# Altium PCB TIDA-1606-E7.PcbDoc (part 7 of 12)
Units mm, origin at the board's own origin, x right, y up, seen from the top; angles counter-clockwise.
Board outline 270 x 345 mm, 4 copper layers (Top Layer, Signal Layer 1, Signal Layer 2, Bottom Layer), stack 2.326 mm thick; 1282 components, 576 nets, 3628 pads, 4132 vias.
Unrouted connection lines stored in the file: 1719.
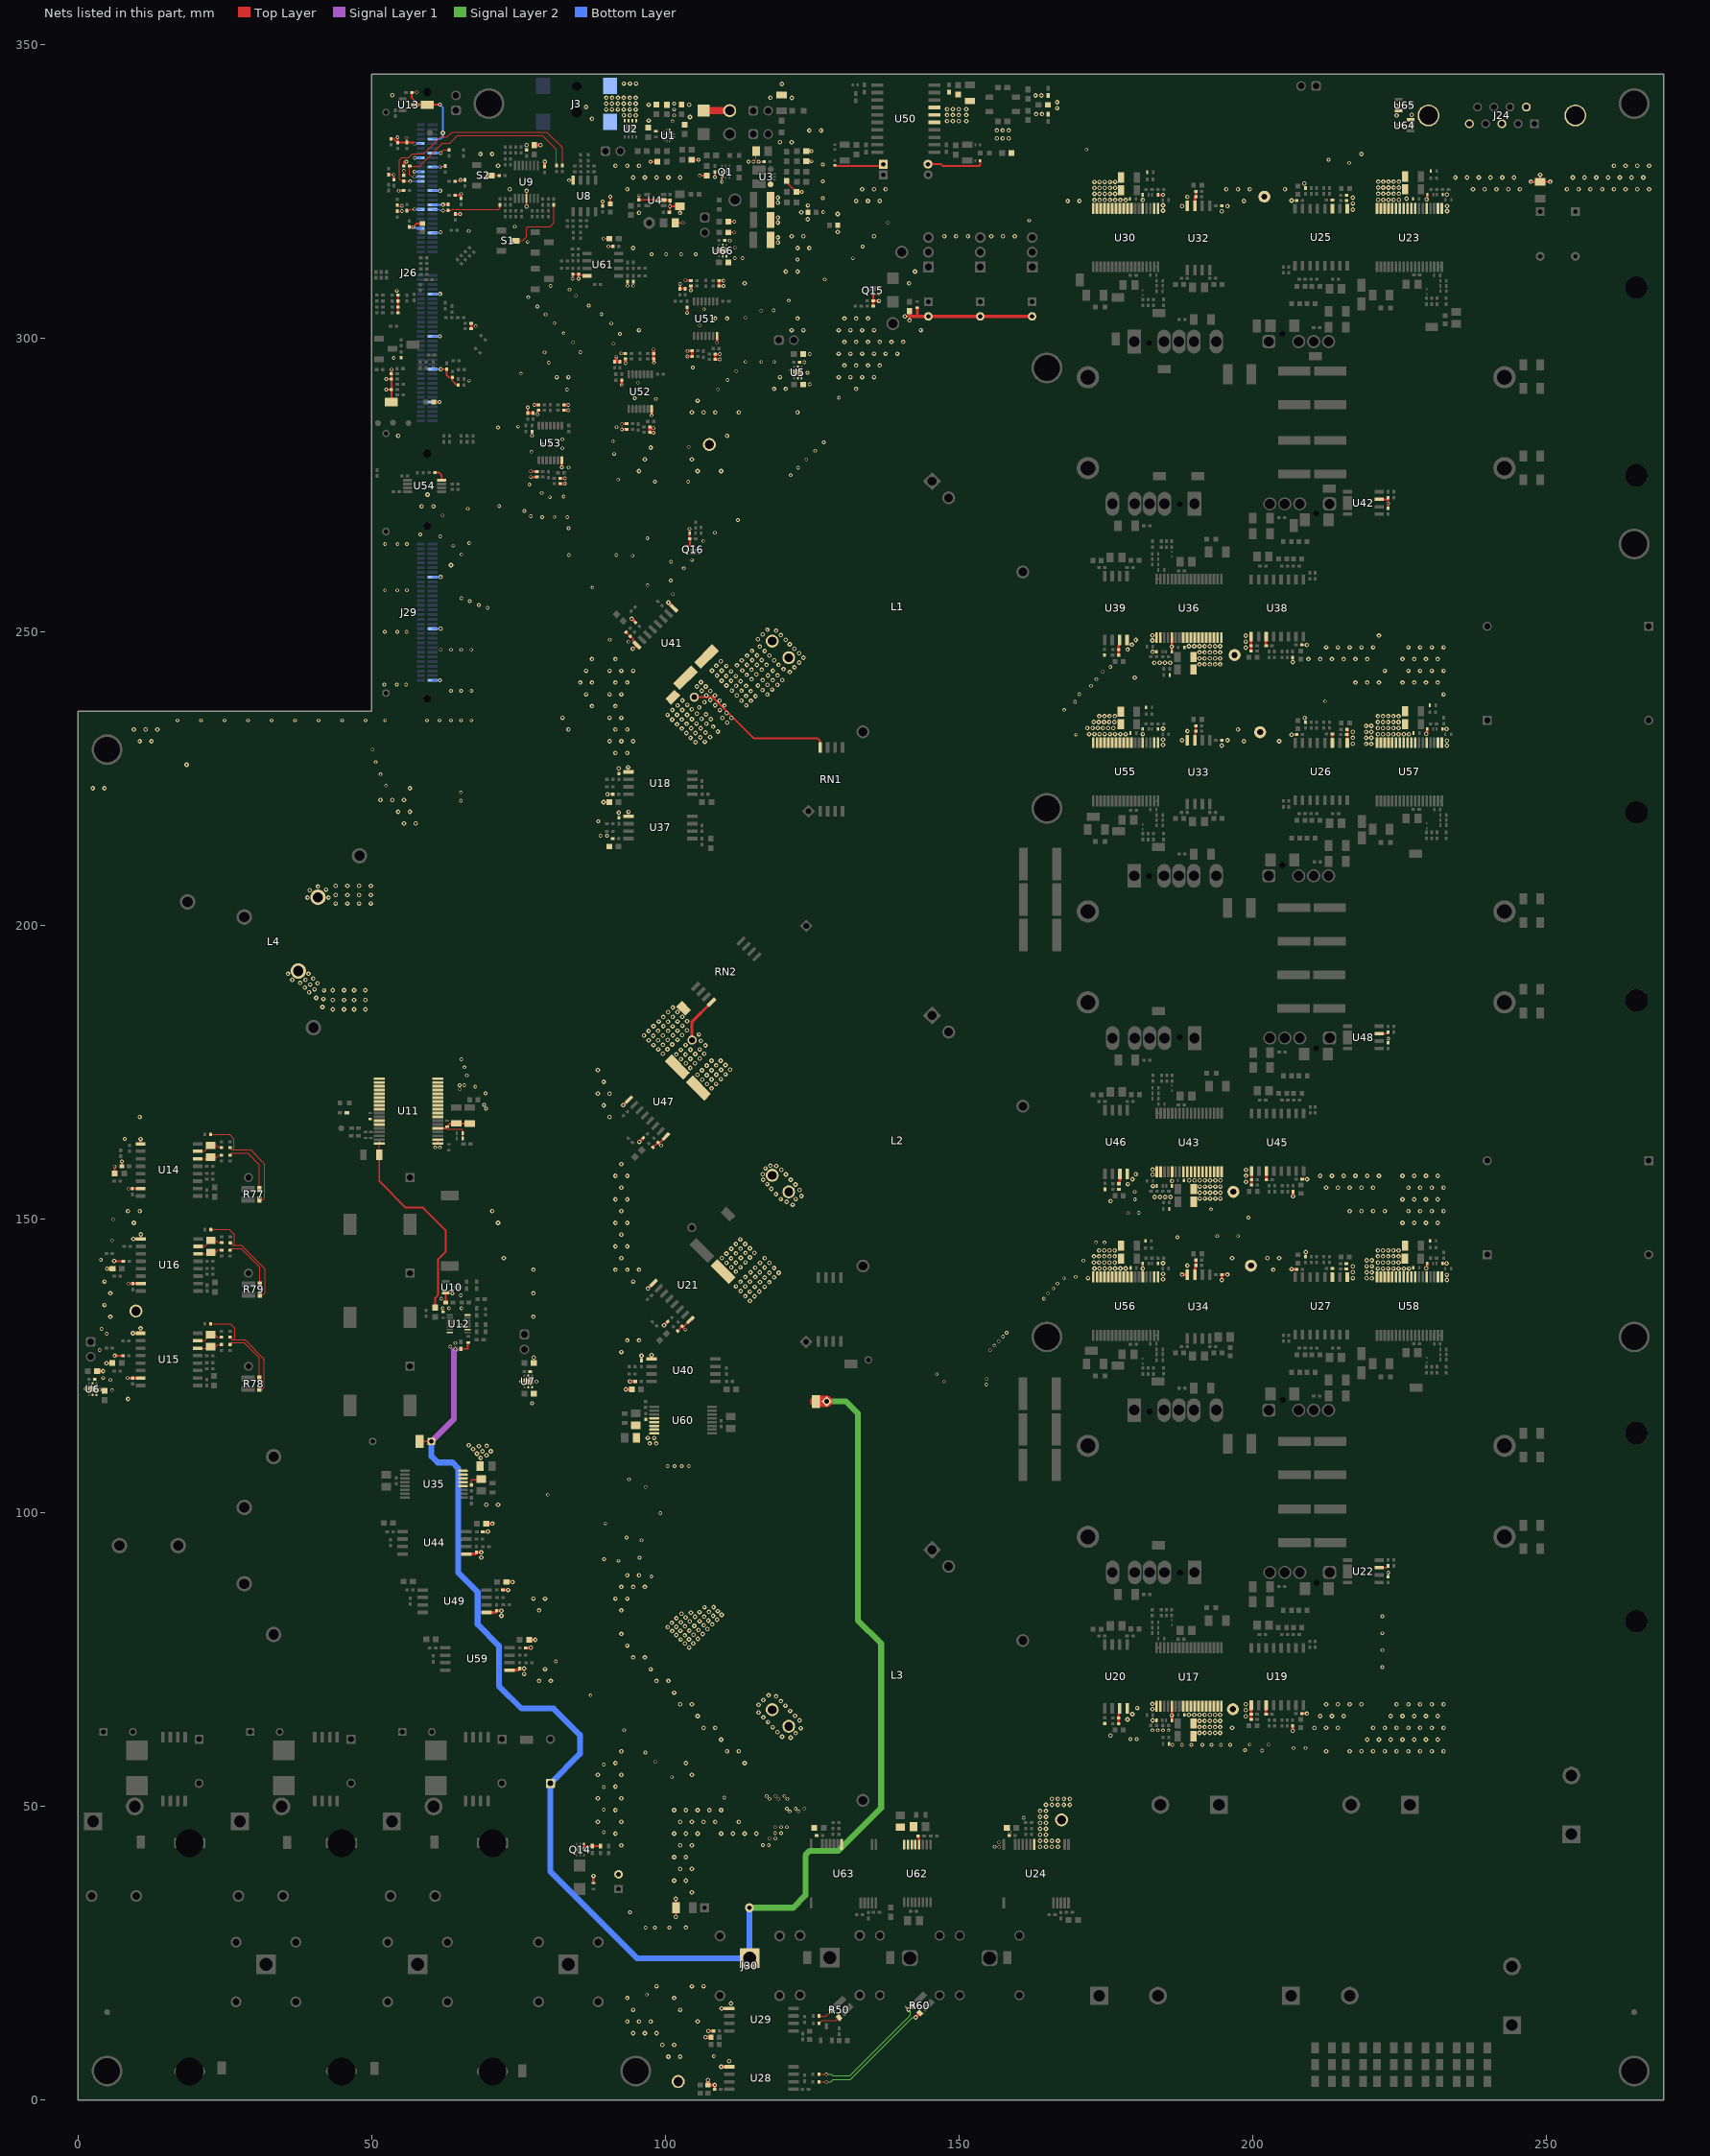
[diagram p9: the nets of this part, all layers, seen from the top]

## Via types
v1: diameter 0.762, hole 0.356, Top Layer to Bottom Layer, tented both sides, 2905 vias
v2: diameter 0.61, hole 0.356, Top Layer to Bottom Layer, tented both sides, 1212 vias
v3: diameter 0.864, hole 0.406, Top Layer to Bottom Layer, tented both sides, 15 vias

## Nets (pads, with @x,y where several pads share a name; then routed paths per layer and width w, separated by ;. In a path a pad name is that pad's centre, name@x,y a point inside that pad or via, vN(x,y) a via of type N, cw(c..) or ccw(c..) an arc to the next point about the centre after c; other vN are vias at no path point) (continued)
GND: C1.2 C2.2 C3.2 C4.2 C5.2 C6.2 C9.2 C10.2 C11.2 C12.2 C13.1 C14.2 C15.2 C16.2 C17.2 C18.2 C19.2 C20.2 C21.1 C22.2 C23.2 C24.2 C25.2 C26.2 C27.2 C28.1 C29.2 C30.2 C31.2 C32.1 C34.2 C58.1 C59.2 C61.2 C62.2 C65.1 C66.2 C85.2 C86.2 C87.2 C94.2 C95.2 C98.2 C102.2 C103.2 C104.2 C107.1 C110.2 C112.1 C116.1 C119.2 C121.1 C125.1 C128.2 C130.1 C132.2 C133.2 C134.2 C143.2 C146.2 C154.2 C155.2 C157.1 C158.2 C159.2 C162.2 C166.2 C168.2 C170.1 C171.2 C172.2 C173.2 C174.2 C180.2 C183.2 C186.2 C194.2 C195.2 C199.2 C207.2 C208.2 C211.1 C212.2 C220.2 C221.2 C225.2 C226.2 C227.2 C229.2 C232.2 C233.2 C234.2 C240.2 C243.2 C246.2 C249.2 C253.2 C256.2 C260.2 C263.2 C267.2 C269.2 C271.2 C274.2 C276.2 C277.2 C278.2 C283.1 C284.2 C285.2 C287.2 C290.2 C292.2 C298.2 C299.2 C301.2 C302.2 C303.2 C306.2 C310.2 C311.2 C312.2 C314.1 C315.1 C317.2 C318.2 C319.2 C320.2 C321.2 C322.1 C323.2 C326.2 C327.2 C328.2 C329.2 C330.2 C333.2 C338.2 C340.1 C341.2 C344.1 C345.1 C346.2 C348.2 C349.2 C351.2 C355.1 C356.2 C358.2 C359.2 C360.2 C363.2 C364.2 C365.2 C366.2 C367.2 C368.2 C369.2 C383.1 C384.1 C385.2 C386.2 C387.2 C388.2 C389.2 C390.2 C391.2 C392.2 C393.1 C394.2 C397.2 C398.2 C399.2 C401.2 C402.2 C405.2 C406.2 C407.2 C409.1 C410.2 C413.2 C414.2 C415.2 C417.2 C418.2 C421.2 C422.2 C423.2 C425.2 C426.2 C429.2 C430.2 C431.2 C432.2 C433.2 C434.2 C435.2 C436.2 C437.2 C438.2 C439.2 C440.2 C441.2 C442.2 C443.2 C444.1 C445.2 C448.2 C449.2 C450.2 C451.2 C452.2 C461.2 C462.2 C463.2 C464.2 C465.2 C466.2 C467.2 C468.2 C469.1 C470.2 C471.2 C472.2 C473.2 C474.2 C475.1 C476.1 C477.1 C478.1 C479.1 C480.1 C481.1 C483.2 C484.2 C485.2 C486.2 C487.2 C488.2 C489.2 C490.2 C492.2 D2.2 FB20.1 J3.2 J3.3 J23.1 J26.10 J26.24 J26.38 J26.56 J26.74 J26.75 J26.83 J26.86 J26.92 J26.99 J26.102 J26.105 J26.108 J26.111 J26.114 J29.2 J29.24 J29.46 L6.1 L9.1 Q1.4 Q1.7 Q14.4 Q14.7 Q15.4 Q15.7 Q16.4 Q16.7 R3.1 R4.1 R8.1 R9.1 R13.1 R14.2 R15.1 R18.1 R19.2 R29.2 R111.1 R115.1 R131.1 R152.1 R158.1 R175.2 R185.2 R193.1 R197.1 R212.1 R227.1 R255.1 R261.2 R265.2 R269.2 R282.1 R288.1 R299.2 R305.2 R314.2 R321.1 R327.1 R337.2 R342.1 R344.2 R375.1 R376.1 R377.1 R378.1 R379.1 R381.1 R389.1 R392.1 R398.1 R403.1 R413.1 R414.1 R415.1 R422.1 R424.1 R434.2 R441.1 R442.1 R443.1 R444.1 R512.1 R532.1 R540.1 TP2.1 TP4.1 TP8.1 TP10.1 TP11.1 TP12.1 TP13.1 TP14.1 TP15.1 TP17.1 TP20.1 TP23.1 TP26.1 U1.8 U2.5 U2.6 U2.7 U2.8 U3.4 U4.2 U5.2 U5.3 U5.5 U5.7@122.588,294.218 U6.2 U6.3 U6.5 U6.7@2.55,121.112 U7.2 U7.3 U7.5 U7.7@76.69,122.401 U8.4 U9.11 U11.1 U11.2 U11.5 U11.8 U11.9 U11.10 U11.11 U11.12 U11.13 U11.14 U11.15 U11.16 U11.17 U11.18 U13.3 U14.9 U14.15 U15.9 U15.15 U16.9 U16.15 U17.1 U17.2 U17.5 U17.8 U17.9 U17.10 U17.11 U17.12 U17.13 U17.14 U17.15 U17.16 U17.17 U17.18 U18.5 U19.9 U19.11 U20.3 U20.4 U21.3 U21.10 U22.3 U23.1 U23.2 U23.5 U23.8 U23.9 U23.10 U23.11 U23.12 U23.13 U23.14 U23.15 U23.16 U23.17 U23.18 U24.9 U25.9 U25.11 U26.9 U26.11 U27.9 U27.11 U28.5 U29.5 U30.1 U30.2 U30.5 U30.8 U30.9 U30.10 U30.11 U30.12 U30.13 U30.14 U30.15 U30.16 U30.17 U30.18 U32.3 U32.4 U33.3 U33.4 U34.3 U34.4 U35.4 U35.5 U35.6 U35.7 U35.8 U36.1 U36.2 U36.5 U36.8 U36.9 U36.10 U36.11 U36.12 U36.13 U36.14 U36.15 U36.16 U36.17 U36.18 U37.5 U38.9 U38.11 U39.3 U39.4 U40.5 U41.3 U41.10 U42.3 U43.1 U43.2 U43.5 U43.8 U43.9 U43.10 U43.11 U43.12 U43.13 U43.14 U43.15 U43.16 U43.17 U43.18 U44.5 U45.9 U45.11 U46.3 U46.4 U47.3 U47.10 U48.3 U49.5 U51.7 U52.7 U53.7 U54.4 U55.1 U55.2 U55.5 U55.8 U55.9 U55.10 U55.11 U55.12 U55.13 U55.14 U55.15 U55.16 U55.17 U55.18 U56.1 U56.2 U56.5 U56.8 U56.9 U56.10 U56.11 U56.12 U56.13 U56.14 U56.15 U56.16 U56.17 U56.18 U57.1 U57.2 U57.5 U57.8 U57.9 U57.10 U57.11 U57.12 U57.13 U57.14 U57.15 U57.16 U57.17 U57.18 U58.1 U58.2 U58.5 U58.8 U58.9 U58.10 U58.11 U58.12 U58.13 U58.14 U58.15 U58.16 U58.17 U58.18 U59.5 U60.4 U60.5 U60.6 U60.7 U60.8 U61.4 U62.4 U62.5 U62.6 U62.7 U62.8 U63.9 U66.2 U66.3 U66.5 U66.7@109.817,314.983 | length 350.7
  Top Layer w0.203: C490.2@54.402,321.7 v2(55.186,321.7) ; C485.2@54.402,322.585 v2(55.178,322.585) ; v2(54.647,325.185) C358.2@55.469,325.185 ; C227.2@55.502,327.785 v2(55.502,328.586) ; C487.2@56.002,321.785 56.37,321.785 56.584,321.999 v2(57.317,321.999) ; v2(61.688,329.185) 61.873,329.37 C61.2@62.602,329.37 ; v2(61.802,331.585) 62.309,332.092 C240.2@63.202,332.092 ; 62.611,165.521 62.778,165.354 65.346,165.354 65.532,165.168 R111.1@65.532,163.802 ; C486.2@64.227,326.8 64.988,326.8 v2(65.188,327) C488.2@65.902,327 ; 66.974,302.117 v2(67.761,302.117) ; v2(83.66,326.954) U8.4@84.347,326.954 ; v2(115.058,330.1) 115.504,330.546 C12.2@115.504,331.894 ; v2(115.914,330.1) C13.1@116.844,330.1
  Top Layer w0.229: v2@8.493,155.239 C107.1@9.331,155.239 9.342,155.25 U14.15@10.691,155.25 ; v1@181.33,141.63 C410.2@181.33,142.505 ; U33.3@190.197,231.6 190.197,232.684 190.377,232.864 C256.2@190.377,233.174 R265.2@190.377,234.071 ; v1@206.87,244.698 v1(206.87,244.898) C298.2@206.87,245.698 ; C299.2@208.418,247.819 v1(209.27,247.819) ; U26.11@213.612,231.14 C477.1@213.612,232.641 ; R212.1@216.095,233.429 216.152,233.372 U26.9@216.152,231.14 ; R540.1@232.356,142.505 v1(233.054,142.505)
  Top Layer w0.254: C103.2@52.902,327.914 v2@53.746,327.914 ; C326.2@53.802,327.025 v2(53.802,327.857) ; C274.2@55.51,329.37 55.51,330.101 55.524,330.115 v2(55.935,330.115) ; C387.2@63.778,293.4 63.778,292.824 64.502,292.1 C386.2@64.802,292.1 ; v1(76.402,322.474) U9.11@76.402,323.868 v1(76.402,325.157) ; v2(84.27,310.177) R19.2@84.27,310.962 C32.1@85.27,310.962 ; v2(85.27,310.198) C32.1@85.27,310.962 ; U61.4@86.702,310.684 85.898,310.684 85.62,310.962 C32.1@85.27,310.962 ; v2(93.597,308.998) C444.1@93.597,309.684 ; v2(94.57,309) R29.2@94.57,309.684 ; v2(109.679,326.695) Q1.7@109.679,328.3 ; R13.1@120.702,326.612 R18.1@122.337,324.977
  Top Layer w0.305: v1(4.9,125.5) 5.844,125.5 C119.2@5.876,125.532 ; v1(5,141.6) 5.913,141.6 C128.2@5.918,141.605 ; v1(6.2,142.9) 7.729,142.9 C130.1@7.754,142.875 ; v1(6.3,126.8) 7.704,126.8 7.709,126.805 C121.1@7.712,126.802 ; C110.2@6.3,158.214 v2(6.3,159) ; C112.1@7.512,159.06 v2(7.512,159.868) ; v1(9.388,130.612) U15.9@10.691,130.612 v1(10.691,131.455) ; v1(9.458,146.685) U16.9@10.733,146.685 v1(10.733,147.455) ; U14.9@10.691,162.87 v1(10.691,163.691) ; v2(52.522,291.3) C392.2@53.402,291.3 ; v2(52.522,293.091) C391.2@53.402,293.091 ; C158.2@53.34,334.016 53.808,334.016 C317.2@54.457,333.367 ; TP15.1@53.402,289.185 C392.2@53.402,291.3 ; v2(53.402,294.711) C390.2@53.402,293.976 C391.2@53.402,293.091 ; v2@53.746,327.914 v2(53.802,327.857) ; v2(54.457,334.284) C317.2@54.457,333.367 ; R444.1@54.524,304.385 R443.1@54.524,305.385 R442.1@54.524,306.385 R441.1@54.524,307.385 ; v2(56.002,334.158) C171.2@56.002,333.385 ; C489.2@56.452,319 57.088,319 v2(57.105,318.983) 57.722,319.6 C168.2@58.702,319.6 ; v2(57.37,333.165) 57.149,333.385 C171.2@56.002,333.385 ; v2(57.722,341.912) C104.2@56.874,341.912 56.874,340.978 57.394,340.459 U13.3@57.394,339.812 59.492,339.812 TP26.1@59.502,339.823 v2(61.658,339.823) ; C34.2@60.634,289.2 61.588,289.2 v2(61.602,289.185) ; C393.1@60.837,277.148 61.533,277.148 61.951,276.73 U54.4@61.951,275.878 ; U11.1@61.293,162.921 U11.2@61.293,163.571 ; U11.5@61.293,165.521 62.611,165.521 C87.2@62.888,165.798 63.435,166.345 C85.2@64.446,166.345 66.721,166.345 C86.2@66.732,166.334 ; v1(61.816,294.785) 62.825,294.785 C388.2@62.84,294.8 62.84,293.764 63.204,293.4 C387.2@63.778,293.4 ; C301.2@64.227,324.376 65.042,324.376 v2(65.278,324.612) C348.2@65.278,323.842 ; C481.1@66.974,302.6 66.974,302.117 R299.2@66.974,301.7 R299.2@66.999,301.725 ; C448.2@67.02,104.767 67.02,105.655 68.556,105.655 C285.2@68.7,105.799 ; R413.1@76.602,287.3 v2(76.602,288.3) ; v2(78.251,287.1) 78.251,287.586 C474.2@78.437,287.772 ; Q14.7@86.202,42.795 86.202,43.3 ; Q14.4@86.202,43.675 86.202,43.3 ; R115.1@89.014,43.3 C98.2@87.627,43.3 86.202,43.3 ; C450.2@89.36,322.554 v2(89.36,323.325) ; v2(89.503,316.998) C31.2@90.502,316.998 ; v2(90.331,315.698) C30.2@91.102,315.698 ; C451.2@90.66,322.954 v2(90.66,324.153) ; R314.2@93.35,249.993 94.065,249.278 C429.2@94.093,249.278 94.535,248.837 94.535,248.476 U41.10@95.214,247.797 94.584,247.167 v1(94.488,247.167) ; v2(95.532,324.37) C314.1@95.532,323.62 99.666,323.62 U4.2@99.716,323.57 100.775,323.57 C15.2@100.845,323.5 v2(100.845,322.526) ; v1(97.069,138.232) 98.002,139.164 U21.3@98.032,139.164 ; v2(97.539,330.1) R8.1@98.706,330.1 ; R344.2@97.935,162.256 C430.2@98.807,163.128 ; v2(99.337,162.598) C430.2@98.807,163.128 ; U47.10@100.132,164.12 99.14,163.128 C430.2@98.807,163.128 ; C20.2@100.721,321.5 100.845,321.624 v2(100.845,322.526) ; C21.1@101.753,319.7 v2(103.036,319.7) ; v1(101.833,31.232) L6.1@101.833,32.8 v1(101.833,34.29) ; R185.2@102.122,131.014 C425.2@102.907,131.8 ; v1(102.54,321.4) C16.2@102.54,322.526 v2(100.845,322.526) ; v2(103.457,131.25) C425.2@102.907,131.8 ; Q16.4@103.825,264.693 104.237,264.693 ; v2(104.167,267.593) R434.2@104.167,266.835 104.167,265.926 C394.2@104.205,265.888 104.205,264.724 104.237,264.693 ; U21.10@104.318,132.878 103.24,131.8 C425.2@102.907,131.8 ; R4.1@104.525,330.448 v2(105.702,330.448) ; Q16.7@104.705,264.693 104.237,264.693 ; v2(105.903,327.77) R9.1@107.076,327.77 ; v2(108.479,327.5) C6.2@108.479,328.37 ; C452.2@110.793,318.06 v2(111.798,318.06) ; R15.1@110.793,319.902 v2(111.798,319.902) ; R13.1@120.702,326.612 R13.1@120.702,326.817 ; R18.1@122.337,324.977 v2(123.28,324.977) ; R14.2@124.045,330.171 v2@124.874,330.171 ; C14.2@124.045,331.894 v2(124.902,331.894) ; FB20.1@128.88,329.503 128.88,329.397 J23.1@137.142,329.397 ; R131.1@135.425,305.5 C417.2@135.425,306.4 ; Q15.4@136.375,307.525 Q15.7@135.495,307.525 135.425,307.455 C417.2@135.425,306.4 ; v1(136.4,306.4) C417.2@135.425,306.4 ; v1(140.825,303.775) 141.6,303.775 v1(141.6,303.1) ; C368.2@144.729,303.868 C368.2@144.822,303.775 ; C287.2@186.274,246.646 v1(186.274,247.536) ; U22.3@221.6,90.708 C340.1@223.011,90.708 ; U48.3@221.6,181.629 C345.1@222.988,181.629 ; U42.3@221.6,272.63 222.987,272.63 223.117,272.5 ; C170.1@223.1,271.1 223.117,271.117 v2(223.117,271.9) 223.117,272.5 ; C344.1@223.117,272.9 223.117,272.5 ; v1(247.421,326.705) L9.1@249,326.705 ; v1(249,327.895) L9.1@249,326.705 ; v1(250.696,326.705) L9.1@249,326.705 ; C392.2@53.402,291.3 C391.2@53.402,293.091 ; C317.2@54.457,333.367 55.984,333.367 C171.2@56.002,333.385
  Top Layer w0.35: v2(8.5,122.992) C116.1@9.342,122.992 U15.15@10.691,122.992 ; v2(8.6,139.065) C125.1@9.363,139.065 U16.15@10.733,139.065 ; C292.2@143.085,45.014 143.085,44.692 143.277,44.5 U62.4@143.277,43.555 ; v1(229.602,141.694) 229.746,141.838 C426.2@229.746,142.505 ; v1(229.602,232.689) 229.746,232.833 C418.2@229.746,233.5 ; v1(229.65,323.694) 229.794,323.838 C183.2@229.794,324.505
  Top Layer w0.4: C22.2@3.3,124.161 v1(4.3,124.161) ; v1(62.175,322.785) 62.231,322.842 C329.2@63.036,322.842 ; C492.2@64.302,321.2 v2(65.102,321.2) ; v2(77.159,276.42) R414.1@78.162,276.42 ; v2(77.159,277.368) C471.2@78.162,277.368 ; C472.2@82.112,276.188 v2(82.937,276.188) ; R415.1@82.137,275.288 v2(82.936,275.288) ; v2(82.412,278.092) U53.7@82.412,279.273 ; C94.2@87.8,36.998 v1(87.8,38.2) ; v2(92.655,284.529) R389.1@93.452,284.529 ; v2(92.67,285.478) C465.2@93.452,285.478 ; v2(97.702,286.918) U52.7@97.702,288.013 ; v2(102.546,309.279) R375.1@102.546,308.471 C102.2@103.446,308.471 ; v2(103.446,309.882) R378.1@104.396,309.882 ; v2(103.746,304.357) C383.1@103.746,305.331 ; v2(103.804,296.946) R376.1@104.593,296.946 C461.2@104.593,297.895 v2(103.818,297.895) ; v2(104.396,308.22) C464.2@104.396,308.946 ; v1(107.365,11.8) C271.2@108.237,11.8 ; v2(108.843,299.352) U51.7@108.843,300.431 ; v2(109.328,296.446) R377.1@108.546,296.446 108.546,297.343 C462.2@108.543,297.346 v2(109.343,297.346) ; v2(109.927,309.865) R379.1@109.193,309.865 C463.2@109.193,308.945 v2(109.945,308.945) ; R305.2@177.206,246.093 177.219,246.106 C306.2@177.219,247.035 177.219,247.719 177.414,247.914 177.414,248.643 U39.3@177.389,248.668 ; R175.2@177.208,64.132 R175.2@177.221,64.145 C162.2@177.221,65.073 177.221,65.758 177.416,65.952 177.416,66.682 U20.3@177.391,66.707 ; C349.2@177.261,156.069 177.261,156.376 177.439,156.554 U46.3@177.439,157.71 ; U39.4@178.659,248.668 U39.4@178.693,248.702 ; U20.4@178.661,66.707 U20.4@178.677,66.723 ; v1@181.328,323.603 v1(181.333,323.598) ; U56.5@181.33,140.201 v1@181.33,141.63 ; v1(183.036,246.646) R282.1@183.701,246.646 ; R255.1@183.915,324.468 v2(184.773,324.468) ; v1(186.274,247.536) U36.5@186.274,249.085 ; C143.2@186.276,64.685 v1(186.276,65.574) U17.5@186.276,67.124 ; U32.3@190.195,322.568 190.195,323.962 C249.2@190.375,324.142 R261.2@190.375,325.039 ; U34.3@190.197,140.605 190.197,141.655 190.377,141.835 R269.2@190.377,142.178 C263.2@190.377,143.076 ; v1(194.777,139.695) 194.766,139.706 C260.2@194.766,140.605 v1(195.755,140.605) ; R288.1@199.798,246.798 C290.2@199.798,247.719 U38.9@199.798,249.222 ; R158.1@199.8,64.836 C146.2@199.8,65.758 U19.9@199.8,67.261 ; R327.1@199.839,155.832 C333.2@199.839,156.753 U45.9@199.839,158.256 ; C479.1@202.338,247.721 U38.11@202.338,249.222 ; C480.1@202.34,65.76 U19.11@202.34,67.261 ; C475.1@202.379,156.755 U45.11@202.379,158.256 ; v1(206.872,62.936) C154.2@206.872,63.736 ; v1(206.911,153.932) C341.2@206.911,154.732 ; C155.2@208.42,65.858 v1(209.272,65.858) ; C338.2@208.459,156.853 v1(209.312,156.853)
  Top Layer w0.5: U44.5@66.187,93.02 67.62,93.02 C267.2@67.9,93.3 v1(68.7,93.3) ; v1@68.725,92.44 v1@68.725,92.475 ; C211.1@68.95,96.83 v1(69.833,96.83) ; C229.2@69.55,98.2 v1(70.6,98.2) ; U49.5@69.613,83.086 71.047,83.086 C302.2@71.326,83.366 v1(72.126,83.366) ; C283.1@72.376,86.896 v1(73.259,86.896) ; C284.2@72.976,88.266 v1(74.026,88.266) ; U59.5@73.497,73.246 74.93,73.246 C327.2@75.21,73.525 v1(76.01,73.525) ; C322.1@76.26,77.056 v1(77.143,77.056) ; R413.1@76.602,287.3 C470.2@77.502,287.3 ; C323.2@76.86,78.425 v1(77.91,78.425) ; v2(77.34,283.423) C469.1@77.34,284.173 ; v2(77.71,288.707) R424.1@78.437,288.707 ; C311.2@77.734,332.93 v1(78.772,332.93) ; C310.2@79.511,329.303 v1(79.511,330.103) ; C473.2@82.762,287.787 v2(83.537,287.787) ; R422.1@82.762,288.707 v2(83.537,288.707) ; v2(91.694,296.926) 91.694,296.342 R381.1@91.406,296.053 C389.2@92.306,296.053 ; v2(92.531,297.465) R403.1@93.256,297.465 ; v2(92.606,292.07) C384.1@92.606,292.913 ; v1(92.883,169.474) 93.815,170.406 U47.3@93.845,170.406 ; v2(93.256,295.793) C468.2@93.256,296.529 ; v1(93.322,121.065) 93.344,121.043 C356.2@94.33,121.043 ; v1(93.996,122.412) C355.1@94.93,122.412 ; v1(94.3,252.287) 94.329,252.287 C312.2@94.934,251.681 ; v1(95.6,163.2) 95.614,163.2 C328.2@96.293,163.879 ; C359.2@95.989,125.952 v1(95.989,126.791) ; U40.5@97.693,126.222 v1(97.693,126.9) ; v2(98.044,283.972) 97.463,283.972 R392.1@97.406,284.029 97.406,284.926 C466.2@97.402,284.929 97.597,284.734 v2(98.044,284.734) ; v2(98.052,298.133) R398.1@98.052,297.448 C467.2@98.052,296.528 98.1,296.48 v2(98.1,295.91) ; v1(99.828,131.964) 100.446,132.583 C166.2@100.446,132.598 ; v1(100.568,255.045) 100.568,255.015 U41.3@101.5,254.083 ; v1(106.9,10.731) C269.2@107.837,10.731 ; v1(107.3,3.449) C221.2@107.3,2.6 v1(108.456,2.6) C220.2@108.456,1.887 ; v1(109.55,5.697) U28.5@110.95,5.697 ; v1(109.611,15.63) U29.5@110.95,15.63 ; v1(188.016,140.605) U34.4@188.927,140.605 ; v1(206.68,141.547) 206.708,141.519 C226.2@207.53,141.519
  Top Layer w0.508: C401.2@141.6,304.675 141.6,303.775 143,303.775 ; C369.2@142.932,305.259 142.932,303.842 143,303.775 ; C368.2@144.729,303.868 144.636,303.775 143,303.775 ; C368.2@144.822,303.775 C367.2@153.658,303.775 C366.2@162.495,303.775
  Top Layer w1.27: D2.2@106.564,338.8 TP2.1@111.002,338.8
  Bottom Layer w0.203: v2(57.317,321.999) v2@57.331,321.985 ; v2(57.37,333.165) v2@57.391,333.185 ; J26.83@58.388,321.999 J26.83@58.402,321.985
  Bottom Layer w0.305: v2(57.105,318.983) 57.393,318.983 57.591,318.785 J26.75@58.402,318.785 ; v2(57.317,328.385) J26.99@58.402,328.385 ; v2@57.331,321.985 J26.83@58.402,321.985 ; v2(57.387,330.785) J26.105@58.402,330.785 ; v2@57.391,333.185 J26.111@58.402,333.185 ; J29.2@60.402,241.785 v2(61.658,241.785) ; J29.24@60.402,250.585 v1(61.801,250.585) ; J29.46@60.402,259.385 v1(61.788,259.385) ; J26.10@60.402,289.185 v2(61.602,289.185) ; J26.24@60.402,294.785 v1(61.816,294.785) ; J26.38@60.402,300.385 v2(61.688,300.385) ; J26.56@60.402,307.585 v1(61.688,307.585) ; J26.74@60.402,317.985 61.674,317.985 v2(61.801,318.113) ; J26.86@60.402,322.785 v1(62.175,322.785) ; J26.92@60.402,325.185 v1(61.688,325.185) ; J26.102@60.402,329.185 v2(61.688,329.185) ; J26.108@60.402,331.585 v2(61.802,331.585) ; J26.114@60.402,333.985 61.807,333.985 62.171,334.349 v1(62.171,335.026) 62.171,339.31 v2(61.658,339.823)
  other v1: 110.897,6.659 100.548,7.416 102.548,7.416 99.548,9.416 101.548,9.416 94.548,11.416 96.548,11.416 98.548,11.416 93.548,13.416 95.548,13.416 97.548,13.416 105.548,13.416 94.548,15.416 102.548,15.416 111.204,16.495 93.548,17.416 101.548,17.416 98.548,19.416 104.548,19.416 106.548,19.416 103.548,29.416 104.548,35.416 101.548,37.416 103.548,37.416 102.548,39.416 104.548,39.416 101.548,41.416 103.548,41.416 163.83,43.18 164.846,43.18 165.862,43.176 166.878,43.176 92.548,43.416 102.548,43.416 104.548,43.416 163.83,44.196 164.846,44.196 165.862,44.196 166.878,44.192 163.83,45.212 164.846,45.212 91.548,45.416 101.548,45.416 103.548,45.416 105.548,45.416 109.548,45.416 111.548,45.416 113.548,45.416 115.548,45.416 163.83,46.228 164.846,46.228 163.83,47.249 164.846,47.249 88.548,47.416 92.548,47.416 102.548,47.416 104.548,47.416 106.548,47.416 108.548,47.416 112.548,47.416 163.83,48.26 164.846,48.26 163.83,49.276 164.846,49.276 91.548,49.416 101.548,49.416 103.548,49.416 105.548,49.416 107.548,49.416 109.548,49.416 164.846,50.314 165.862,50.314 166.873,50.314 167.894,50.314 168.91,50.314 165.862,51.33 166.873,51.33 167.894,51.33 168.91,51.33 88.548,51.416 92.548,51.416 91.548,53.416 88.548,55.416 92.548,55.416 104.548,55.416 91.548,57.416 103.548,57.416 113.548,57.416 92.548,59.416 110.548,59.416 112.548,59.416 212.548,59.416 216.548,59.416 218.548,59.416 220.548,59.416 222.548,59.416 224.548,59.416 226.548,59.416 228.548,59.416 230.548,59.416 232.548,59.416 109.548,61.416 219.548,61.416 221.548,61.416 223.548,61.416 225.548,61.416 227.548,61.416 229.548,61.416 231.548,61.416 175.829,62.132 190.986,62.565 191.869,62.565 192.761,62.565 193.644,62.565 194.514,62.565 106.548,63.416 108.548,63.416 196.548,63.416 210.548,63.416 212.548,63.416 214.548,63.416 220.548,63.416 222.548,63.416 224.548,63.416 226.548,63.416 228.548,63.416 230.548,63.416 232.548,63.416 190.986,63.565 191.869,63.565 192.761,63.565 193.644,63.565 194.514,63.565 190.986,64.602 191.869,64.602 192.761,64.602 193.644,64.602 194.514,64.602 183.038,64.685 178.73,64.861 105.548,65.416 198.867,65.4 211.548,65.416 213.548,65.416 215.548,65.416 223.548,65.416 225.548,65.416 227.548,65.416 229.548,65.416 231.548,65.416 189.201,65.636 190.084,65.636 190.986,65.636 191.869,65.636 192.761,65.636 193.644,65.636 194.514,65.636 179.563,65.754 198.867,66.437 182.989,66.625 180.389,66.8 102.548,67.416 104.548,67.416 212.548,67.416 214.548,67.416 216.548,67.416 218.548,67.416 224.548,67.416 226.548,67.416 228.548,67.416 230.548,67.416 232.548,67.416 198.867,67.437 182.989,67.495 101.548,69.416 78.548,71.416 80.548,71.416 98.548,71.416 100.548,71.416 76.01,72.6 79.548,73.416 97.548,73.416 94.548,75.416 96.548,75.416 93.548,77.416 92.548,79.416 72.126,82.513 78.548,83.416 92.548,83.416 77.548,85.416 79.548,85.416 91.548,85.416 93.548,85.416 92.548,87.416 94.548,87.416 96.548,87.416 93.548,89.416 95.548,89.416 68.7,92.44 69.548,101.416 71.548,101.416 68.589,109.374 69.596,109.83 67.972,110.123 68.89,110.531 70.332,110.521 67.3,110.893 68.295,111.39 69.634,111.441 66.573,111.539 97.395,111.846 98.458,111.846 97.052,112.793 98.15,112.793 8.548,119.416 77.64,126.5 92.548,127.416 93.548,129.416 95.548,129.416 5.548,133.416 77.548,133.416 4.548,135.416 5.548,137.416 77.548,137.416 4.548,139.416 94.548,139.416 233.103,139.695 184.775,139.814 219.465,139.962 220.335,139.962 217.099,139.987 172,140 233.103,140.565 184.775,140.712 219.465,140.997 220.335,140.997 217.099,141.024 77.548,141.416 91.548,141.416 93.548,141.416 95.548,141.416 203.548,141.416 173.092,141.635 173.962,141.635 174.845,141.635 175.737,141.635 176.62,141.635 177.522,141.635 178.405,141.635 181.335,141.635 221.365,141.632 222.235,141.632 223.117,141.632 224.009,141.632 224.892,141.632 225.795,141.632 226.677,141.632 217.099,142.024 219.465,142.034 220.335,142.034 188.927,142.14 184.775,142.551 173.028,142.674 173.898,142.674 174.781,142.674 175.673,142.674 176.555,142.674 221.365,142.667 222.235,142.667 223.117,142.667 224.009,142.667 224.892,142.667 219.465,143.034 220.335,143.034 72.548,143.416 92.548,143.416 196.548,143.416 202.548,143.416 204.548,143.416 221.365,143.703 222.235,143.703 223.117,143.703 224.009,143.703 224.892,143.703 173.028,143.711 173.898,143.711 174.781,143.711 175.673,143.711 176.555,143.711 209.084,144.424 173.898,144.711 174.781,144.711 175.673,144.711 176.555,144.711 221.365,144.703 222.235,144.703 223.117,144.703 224.009,144.703 224.892,144.703 91.548,145.416 93.548,145.416 92.548,147.416 9.548,149.416 71.548,149.416 91.548,149.416 93.548,149.416 225.548,149.416 227.548,149.416 229.548,149.416 231.548,149.416 8.548,151.416 10.548,151.416 70.548,151.416 92.548,151.416 216.548,151.416 218.548,151.416 220.548,151.416 222.548,151.416 226.548,151.416 228.548,151.416 230.548,151.416 232.548,151.416 175.861,153.119 91.548,153.416 93.548,153.416 225.548,153.416 227.548,153.416 229.548,153.416 231.548,153.416 191.026,153.56 191.909,153.56 192.801,153.56 193.683,153.56 194.553,153.56 183.339,153.832 184.239,153.832 185.139,153.832 186.039,153.832 191.026,154.56 191.909,154.56 192.801,154.56 193.683,154.56 194.553,154.56 92.548,155.416 212.548,155.416 214.548,155.416 216.548,155.416 218.548,155.416 220.548,155.416 226.548,155.416 228.548,155.416 230.548,155.416 232.548,155.416 191.026,155.597 191.909,155.597 192.801,155.597 193.683,155.597 194.553,155.597 183.078,155.68 178.8,156 198.906,156.396 186.316,156.57 189.241,156.632 190.123,156.632 191.026,156.632 191.909,156.632 192.801,156.632 193.683,156.632 194.553,156.632 179.575,156.849 91.548,157.416 93.548,157.416 211.548,157.416 213.548,157.416 215.548,157.416 217.548,157.416 219.548,157.416 221.548,157.416 225.548,157.416 227.548,157.416 229.548,157.416 231.548,157.416 198.906,157.433 183.029,157.62 180.149,157.71 198.906,158.433 183.029,158.49 92.548,159.416 10.548,167.416 90.548,167.416 89.548,169.416 88.548,171.416 90.548,171.416 89.548,173.416 88.548,175.416 55.548,217.416 57.548,217.416 92.12,219.255 54.548,219.416 56.548,219.416 93.75,219.4 89.522,221.065 51.548,221.416 53.548,221.416 55.548,221.416 90.196,222.412 2.548,223.416 4.548,223.416 56.548,223.416 92.1,226.8 93.7,227 18.548,227.416 91.548,229.416 93.548,229.416 194.777,230.69 233.103,230.69 184.775,230.809 219.365,230.962 220.235,230.962 217.099,230.983 10.548,231.416 12.548,231.416 90.548,231.416 92.548,231.416 94.548,231.416 198.548,231.416 204.548,231.416 233.103,231.56 188.016,231.6 195.755,231.6 184.775,231.707 219.365,231.997 220.235,231.997 217.099,232.02 206.68,232.543 172.199,232.632 173.092,232.63 173.962,232.63 174.845,232.63 175.737,232.63 176.62,232.63 177.522,232.63 178.405,232.63 181.335,232.63 221.365,232.627 222.235,232.627 223.117,232.627 224.009,232.627 224.892,232.627 225.795,232.627 226.677,232.627 217.099,233.02 219.365,233.034 220.235,233.034 188.927,233.135 9.548,233.416 11.548,233.416 13.548,233.416 83.548,233.416 91.548,233.416 93.548,233.416 197.548,233.416 233.054,233.5 184.775,233.547 171.892,233.662 172.796,233.664 173.666,233.664 174.549,233.664 175.441,233.664 176.324,233.664 221.365,233.662 222.235,233.662 223.117,233.662 224.009,233.662 224.892,233.662 219.365,234.034 220.235,234.034 172.974,234.696 173.844,234.696 174.727,234.696 175.619,234.696 176.502,234.696 221.365,234.699 222.235,234.699 223.117,234.699 224.009,234.699 224.892,234.699 208.896,235.4 82.548,235.416 90.548,235.416 92.548,235.416 173.924,235.699 174.807,235.699 175.699,235.699 176.582,235.699 221.365,235.699 222.235,235.699 223.117,235.699 224.009,235.699 224.892,235.699 87.548,237.416 91.548,237.416 86.548,239.416 90.548,239.416 92.548,239.416 232.548,239.416 85.548,241.416 87.548,241.416 91.548,241.416 93.548,241.416 217.548,241.416 219.548,241.416 221.548,241.416 225.548,241.416 227.548,241.416 229.548,241.416 231.548,241.416 179.958,242.244 86.548,243.416 90.548,243.416 92.548,243.416 94.548,243.416 222.548,243.416 226.548,243.416 228.548,243.416 230.548,243.416 232.548,243.416 190.984,244.526 191.867,244.526 192.759,244.526 193.642,244.526 194.512,244.526 183.298,244.798 184.198,244.798 185.098,244.798 185.998,244.798 87.548,245.416 91.548,245.416 209.548,245.416 211.548,245.416 213.548,245.416 215.548,245.416 217.548,245.416 219.548,245.416 225.548,245.416 227.548,245.416 229.548,245.416 231.548,245.416 190.984,245.526 191.867,245.526 192.759,245.526 193.642,245.526 194.512,245.526 190.984,246.563 191.867,246.563 192.759,246.563 193.642,246.563 194.512,246.563 178.751,247.056 198.865,247.362 212.548,247.416 214.548,247.416 216.548,247.416 218.548,247.416 220.548,247.416 226.548,247.416 228.548,247.416 230.548,247.416 232.548,247.416 189.199,247.598 190.082,247.598 190.984,247.598 191.867,247.598 192.759,247.598 193.642,247.598 194.512,247.598 179.474,247.868 198.865,248.399 182.987,248.586 180.149,248.668 198.865,249.399 221.548,249.416 182.987,249.456 63.548,261.416 58.548,271.416 60.548,271.416 59.548,273.416 95.548,277.416 105.548,277.416 109.548,277.416 96.548,279.416 104.548,279.416 97.548,281.416 54.548,283.416 110.548,283.416 104.548,287.416 106.548,287.416 108.548,287.416 112.548,287.416 122.548,287.416 105.548,289.416 118.548,291.416 120.548,291.416 132.548,291.416 81.548,293.416 83.548,293.416 119.548,293.416 129.548,293.416 131.548,293.416 133.548,293.416 135.548,293.416 130.548,295.416 132.548,295.416 134.548,295.416 136.548,295.416 129.548,297.416 131.548,297.416 133.548,297.416 135.548,297.416 137.548,297.416 139.548,297.416 130.548,299.417 132.548,299.417 134.548,299.417 136.548,299.417 138.548,299.417 140.548,299.417 95.548,301.417 121.548,301.417 123.548,301.417 129.548,301.417 131.548,301.417 133.548,301.417 135.548,301.417 143.548,301.417 108.548,303.417 110.548,303.417 122.548,303.417 130.548,303.417 132.548,303.417 134.548,303.417 113.548,309.417 141.548,309.417 120.548,311.417 122.548,311.417 142.548,311.417 94.548,315.417 122.548,315.417 124.548,315.417 119.202,316.344 119.202,317.2 121.548,317.417 123.548,317.417 135.548,317.417 147.548,317.417 149.548,317.417 151.548,317.417 155.548,317.417 157.548,317.417 159.548,317.417 129.388,318.16 119.202,319.744 124.3,320.319 119.202,320.6 129.388,321.208 95.548,321.417 123.19,321.485 194.775,321.659 233.151,321.695 184.773,321.778 217.097,321.951 188.014,322.568 195.753,322.568 233.151,322.565 124.308,322.656 184.773,322.676 217.097,322.988 119.202,323.144 132.548,323.417 134.548,323.417 136.548,323.417 168.548,323.417 170.548,323.417 198.548,323.417 206.678,323.511 173.09,323.598 173.96,323.598 174.843,323.598 175.735,323.598 176.618,323.598 177.52,323.598 178.403,323.598 221.413,323.632 222.283,323.632 223.165,323.632 224.057,323.632 224.94,323.632 226.244,323.838 217.097,323.988 119.202,324 188.925,324.103 233.102,324.505 173.09,324.633 173.96,324.633 174.843,324.633 175.735,324.633 176.618,324.633 221.413,324.667 222.283,324.667 223.165,324.667 224.057,324.667 224.94,324.667 73.548,325.417 93.548,325.417 133.548,325.417 135.548,325.417 137.548,325.417 195.548,325.417 197.548,325.417 199.548,325.417 205.548,325.417 237.548,325.417 239.548,325.417 241.548,325.417 243.548,325.417 245.548,325.417 253.548,325.417 255.548,325.417 257.548,325.417 259.548,325.417 261.548,325.417 263.548,325.417 265.548,325.417 267.548,325.417 173.09,325.67 173.96,325.67 174.843,325.67 175.735,325.67 176.618,325.67 221.413,325.704 222.283,325.704 223.165,325.704 224.057,325.704 224.94,325.704 208.854,326.401 173.09,326.67 173.96,326.67 174.843,326.67 175.735,326.67 176.618,326.67 221.413,326.704 222.283,326.704 223.165,326.704 224.057,326.704 224.94,326.704 94.548,327.417 96.548,327.417 98.548,327.417 100.548,327.417 102.548,327.417 234.548,327.417 236.548,327.417 238.548,327.417 240.548,327.417 242.548,327.417 244.548,327.417 254.548,327.417 256.548,327.417 258.548,327.417 260.548,327.417 262.548,327.417 264.548,327.417 266.548,327.417 71.548,329.417 91.548,329.417 93.548,329.417 95.548,329.417 261.548,329.417 263.548,329.417 265.548,329.417 267.548,329.417 68.548,331.417 70.548,331.417 218.548,331.417 76.411,332.922 119.548,333.417 121.548,333.417 124.548,335.417 126.548,335.417 97.199,337.119 87.548,337.417 104.22,337.716 92.978,338 94.002,338 95.009,338 89.978,339 90.955,339 91.955,339 92.955,339 94.002,339 95.009,339 86.548,339.417 104.1,339.81 97.213,339.823 89.978,340.003 90.955,340.003 91.955,340.003 92.955,340.003 94.002,340.003 95.009,340.003 121.59,340.98 90.002,341 90.978,341 91.978,341 92.955,341 94.002,341 95.009,341 117.937,341.02 53.548,341.417 119.872,343.357 92.978,343.408 94.026,343.408 95.033,343.408
  other v2: 108.295,7.488 96.902,17.995 96.669,29.416 98.25,29.416 100.726,29.416 94.026,32 156.108,43.155 156.87,43.155 116.636,43.449 117.652,43.449 156.8,43.889 117.741,44.566 118.757,44.566 118.734,45.5 119.75,45.5 89.569,45.663 158.683,45.709 118.734,46.516 119.76,46.516 120.734,46.516 161.05,48.124 121.229,49.193 122.734,49.193 89.569,49.501 120.729,49.666 122.229,49.666 123.729,49.692 117.805,51.343 119.31,51.343 120.805,51.343 110.084,51.548 117.305,51.816 118.805,51.816 120.305,51.816 89.569,53.34 101.153,55 89.569,57.179 98.323,57.634 96.635,59.218 201.643,59.557 198.738,59.634 206.992,60 209.039,60 186.367,60.519 188.021,60.519 189.598,60.519 191.464,60.519 193.042,60.519 194.638,60.519 196.216,60.519 199.548,60.561 202.701,60.561 179.237,61.495 180.306,61.495 183,63 183.9,63 184.8,63 185.7,63 93.038,63.022 87.3,68.962 222.113,73.775 81.402,74.733 222.113,76.656 222.113,79.538 222.113,82.419 97.638,89.198 223.117,89.87 92.061,91.877 89.6,92.126 95.641,92.4 95.989,95.377 93.444,95.802 89.805,98.248 99.213,99.991 80.024,103.118 96.672,104.445 93.873,105.734 100.441,108 101.633,108 102.824,108 104.016,108 77.362,118.695 5.818,120.917 3.74,121.019 1.397,121.133 154.686,121.895 75.481,122.387 78.076,122.401 147.498,122.412 5.55,122.642 154.762,122.809 4.324,123 146.242,123.636 155.341,127.733 3.7,127.777 156.074,128.516 156.8,129.277 157.532,130.061 4.933,130.519 158.166,130.702 4.033,131.345 164.5,136.5 165.218,137.438 166.1,138.266 166.807,139.065 167.894,139.98 169.927,140.21 171.238,142.982 3.933,143.104 173.384,146.079 174.828,146.079 5.844,146.431 187.239,146.944 193.995,147.172 197.548,147.172 6.006,150.029 199.323,150.325 178.85,151.089 180.657,151.128 192.945,151.721 179.987,153.416 179.973,154.68 8.6,155.239 60.835,162.257 61.658,162.257 8,163.691 69.508,168.836 69.176,169.516 69.449,171.484 65.064,172.147 67.695,172.627 65.024,172.854 65.802,172.854 66.255,174.518 65.82,175.9 65.318,177.254 223.117,180.791 89.002,215.323 90.1,215.323 88.627,217.8 65.211,221.29 65.225,222.709 52.477,223.854 51.548,225.815 50.722,227.855 50.185,230.001 169.971,232.548 17,235 20.989,235 24.989,235 28.989,235 33,235 37,235 41,235 45,235 49.011,235 52.335,235 59.477,235 61.602,235 63.545,235 65.28,235 67,235 167.95,236.76 169.8,238.114 212.372,238.25 170.534,239.416 63.545,240 65.28,240 67,240 172.517,240.876 52.185,241.076 54.306,241.076 55.901,241.076 173.428,242 174.535,243.245 175.819,244.085 61.782,247 63.545,247 65.28,247 67,247 93.75,248.388 90.602,248.705 52.261,250.044 54.383,250.044 55.978,250.044 69.794,254.142 68.3,254.639 66.732,255.267 65.314,255.788 101.341,256.469 52.335,257.127 54.383,257.127 56.051,257.127 87.627,257.596 97.01,258 100.949,258.789 103.158,260.864 101,261.978 104.58,262.286 94.452,263 83.598,263.118 91.679,263.118 65.322,263.237 63.902,264.738 52.335,265 54.457,265 56.051,265 66.63,265.168 106.498,265.534 96.986,266 61.71,266.322 58.338,266.638 108.466,266.918 83.56,267.688 112.386,269.074 79.073,269.592 81.137,269.611 83.349,269.592 77.138,269.748 62.114,269.86 76.034,270.64 66.4,271 71.74,271.462 80.4,272.987 82.724,273.105 78.971,273.696 76.886,275.118 98.272,275.607 103.945,275.607 92,276 121.388,276.707 122.657,278 83.56,278.043 124.045,279.416 91.324,280.341 77.236,280.715 125.568,280.888 82.513,281.3 104.016,281.535 79,282 80.548,282 127.03,282.318 91.099,282.518 82.513,282.862 71.557,284.85 91.748,284.884 74.964,285 98.437,289.715 94.848,289.834 129.619,289.936 83.291,291.318 109.008,291.344 124.604,292.2 95.359,292.504 66.601,292.842 110.646,292.961 75.427,294.032 124.23,294.169 112.111,294.442 121.437,294.626 104.722,295.058 80.182,295.883 123.72,295.963 113.684,296 116.383,296 118.549,296 53.802,296.7 124.604,297.343 79.486,297.636 85.554,297.7 91.212,299.118 84.347,299.352 92.302,300.774 82.724,300.893 105.917,302.218 90.83,302.539 81.136,302.616 113.664,303.523 79.661,304.087 89.138,304.127 116.367,304.75 118.499,304.786 106.621,305.003 78.235,305.458 87,305.6 121.048,306.448 76.702,307.018 84.836,307.283 54.302,308.114 83.724,308.339 80.486,308.943 127.178,310.058 122.548,313.451 131.965,313.669 111.883,313.713 113.182,313.713 97.69,314.346 100.202,314.346 102.713,314.346 105.224,314.346 108.581,314.949 111.883,315.443 133.629,315.671 76.6,316.452 111.016,316.678 66.573,318.3 74.41,319.047 137.922,319.71 161.996,320.123 126.924,321.524 126.848,323.92 126.848,326.771 126.848,329.622 216.47,329.91 114.202,330.1 124.902,330.171 212.972,330.451 171.735,332.208 101.242,337 101.534,338 101.534,339 101.534,340.003
GND_ISO_CAN: C374.2 C375.2 C376.2 C377.2 C378.1 C379.1 FB19.2 J23.2 J24.3 J24.5 J24.6 J24.10 J24.11 R382.1 U50.15 U50.16 U50.17 U64.2 U65.2 | length 10.2
  Top Layer w0.305: J23.2@145.052,329.397 J23.2@144.762,329.688 147.008,329.688 147.299,329.397 153.478,329.397 153.641,329.56 FB19.2@153.641,330.271
  other v1: 156.473,334.081 157.48,334.081 158.528,334.081 156.473,335.45 157.48,335.45 158.528,335.45 227.149,336.413 148,337.008 148.997,337.008 150.013,337.008 151.282,337.008 224.562,337.988 148,338.055 148.997,338.055 150.013,338.055 151.282,338.055 227.149,338.074 163.173,338.223 164.169,338.223 148,339.063 148.997,339.063 150.013,339.063 151.282,339.063 166.753,339.246 224.562,339.657 166.753,340.242 163.072,341.379 164.069,341.379
GRID_GND: C74.1 C80.1 C89.2 C90.2 C92.2 C96.2 C97.2 J6.2 J30.1 NT17.1 R61.1 R67.2 R74.1 R100.1 TP7.1 TP39.1 U10.2 U11.19 U11.20 U11.21 U11.22 U11.23 U11.24 U11.25 U11.26 U11.27 U11.30 U11.31 U11.36 U12.7 U12.9 U12.14 | length 307.7
  Top Layer w0.203: U11.36@51.343,162.921 51.343,161.007 C90.2@51.35,161
  Top Layer w0.305: C90.2@51.343,161.007 51.343,156.519 55.862,152 58.806,152 62.634,148.172 62.634,144.469 61.339,143.173 61.339,137.132 60.862,136.656 C97.2@60.862,134.993 ; TP7.1@58.166,112.196 C80.1@60.215,112.196 ; R67.2@62.649,135.846 U10.2@62.649,137.501 ; R74.1@65.246,127.967 66.387,127.967 66.389,127.968 C96.2@66.389,129.072
  Top Layer w2: TP39.1@125.691,119.001 C74.1@127.531,119.001
  Signal Layer 1 w1: C80.1@60.215,112.196 64.046,116.027 64.046,127.63 v2(64.288,127.872)
  Signal Layer 2 w1: J6.2@114.358,32.788 121.806,32.788 123.909,34.891 123.909,41.757 124.627,42.475 129.478,42.475 136.782,49.779 136.782,77.772 132.8,81.754 132.8,117 130.799,119.001 C74.1@127.531,119.001
  Bottom Layer w1: C80.1@60.215,112.196 60.215,109.652 61.267,108.6 63.811,108.6 64.77,107.641 64.77,89.857 68.08,86.548 68.08,81.054 71.7,77.434 71.7,70.566 75.559,66.707 81.003,66.707 85.5,62.21 85.5,59.011 R100.1@80.468,53.979 80.468,38.932 95.215,24.185 J30.1@114.426,24.185 ; J6.2@114.358,32.788 114.358,24.442 J30.1@114.426,24.374
  other v2: 63.436,128.331 64.288,128.941 65.211,131.936 62.139,134.869 63.196,134.869 65.322,134.869 61.86,136.483 65.233,137.069 63.811,137.406
I_MID+: R50.E1 R271.2 | length 3.8
  Top Layer w0.203: R271.2@126.218,13.09 126.723,13.595 129.123,13.595 R50.E1@129.615,14.087
I_MID-: R50.E2 R275.2 | length 2.6
  Top Layer w0.203: R275.2@126.218,14.36 127.384,14.36 R50.E2@128.363,15.339
I_NEG_RAIL+: R60.E1 R238.1 | length 22.1
  Top Layer w0.203: R238.1@126.176,3.119 127.45,3.119 v2(127.462,3.131)
  Top Layer w0.5: v1(142.672,14.116) R60.E1@143.397,14.84
  Signal Layer 2 w0.203: v2(127.462,3.131) 128.179,3.131 128.598,3.55 131.55,3.55 142.116,14.116 v1(142.672,14.116)
I_NEG_RAIL-: NT9.2 R60.E2 R243.1 | length 22.5
  Top Layer w0.203: R243.1@126.176,4.427 v2(127.462,4.427) ; NT9.2@141.01,15.848 v1(141.423,15.434)
  Top Layer w0.5: v1(141.423,15.434) R60.E2@142.079,16.091
  Signal Layer 2 w0.203: v2(127.462,4.427) 128.279,4.427 128.506,4.2 131.45,4.2 141.75,14.5 141.75,15.107 v1(141.423,15.434)
I_PCC_INN_L1: C113.2 R136.2 U14.7 | length 4.6
  Top Layer w0.203: U14.7@20.441,161.6 21.604,161.6 C113.2@22.62,162.616 23.654,162.616 24.057,162.213 R136.2@24.456,162.213
I_PCC_INN_L2: C122.2 R141.2 U15.7 | length 4.6
  Top Layer w0.203: U15.7@20.441,129.342 21.604,129.342 C122.2@22.62,130.358 23.425,130.358 23.828,129.955 R141.2@24.456,129.955
I_PCC_INN_L3: C131.2 R146.2 U16.7 | length 4.6
  Top Layer w0.203: U16.7@20.483,145.415 21.646,145.415 C131.2@22.662,146.431 23.535,146.431 23.938,146.028 R146.2@24.498,146.028
I_PCC_INP_L1: C113.1 R134.2 U14.6 | length 4.3
  Top Layer w0.203: U14.6@20.441,160.33 22.366,160.33 C113.1@22.62,160.584 23.667,160.584 24.039,160.956 R134.2@24.456,160.956
I_PCC_INP_L2: C122.1 R139.2 U15.6 | length 4.3
  Top Layer w0.203: U15.6@20.441,128.072 22.366,128.072 C122.1@22.62,128.326 23.509,128.326 23.881,128.698 R139.2@24.456,128.698
I_PCC_INP_L3: C131.1 R144.2 U16.6 | length 4.3
  Top Layer w0.203: U16.6@20.483,144.145 22.408,144.145 C131.1@22.662,144.399 23.512,144.399 23.885,144.771 R144.2@24.498,144.771
I_PCC_L1+: FB1.1 R77.E1 | length 10.1
  Top Layer w0.203: FB1.1@25.912,160.956 26.212,161.256 28.952,161.256 30.932,159.276 R77.E1@30.932,155.154
I_PCC_L1-: FB2.1 FB3.1 R77.E2 | length 20
  Top Layer w0.203: FB3.1@22.62,164.456 25.812,164.456 26.612,163.656 26.612,161.834 ; FB2.1@25.927,162.203 26.296,161.834 26.612,161.834 ; R77.E2@30.932,153.384 31.549,153.384 31.842,153.677 31.842,159.396 29.404,161.834 26.612,161.834
I_PCC_L2+: FB4.1 R78.E1 | length 9.8
  Top Layer w0.203: FB4.1@25.912,128.698 26.249,129.035 28.325,129.035 30.932,126.427 R78.E1@30.932,122.896
I_PCC_L2-: FB5.1 FB6.1 R78.E2 | length 19.5
  Top Layer w0.203: FB6.1@22.62,132.198 26.02,132.198 26.754,131.464 26.754,129.535 ; FB5.1@25.927,129.945 26.337,129.535 26.754,129.535 ; R78.E2@30.932,121.126 31.45,121.126 31.766,121.442 31.766,126.202 28.433,129.535 26.754,129.535
I_PCC_L3+: FB7.1 R79.E1 | length 9.4
  Top Layer w0.203: FB7.1@25.954,144.771 26.254,145.071 27.779,145.071 30.974,141.876 R79.E1@30.974,138.969
I_PCC_L3-: FB8.1 FB9.1 R79.E2 | length 18.9
  Top Layer w0.203: FB9.1@22.662,148.271 25.767,148.271 26.654,147.384 26.654,145.649 ; FB8.1@25.969,146.018 26.338,145.649 26.654,145.649 ; R79.E2@30.974,137.199 31.591,137.199 31.884,137.492 31.884,141.541 27.776,145.649 26.654,145.649
I_SENSE_SN_L1: R310.2 S2.2 | length 1.6
  Top Layer w0.203: S2.2@70.202,327.775 R310.2@71.759,327.775
I_SENSE_SN_L2: C329.1 J26.84 R347.2 | length 12.5
  Top Layer w0.203: v2(62.202,321.799) 63.502,321.799 63.702,322 71.692,322 71.868,322.176 R347.2@71.868,322.761
  Bottom Layer w0.203: J26.84@60.588,321.799 J26.84@60.402,321.985 61.451,321.985 61.638,321.799 v2(62.202,321.799)
I_SENSE_SN_L3: R180.2 S1.2 | length 11.8
  Top Layer w0.203: S1.2@74.402,316.65 75.726,316.65 76.379,317.303 76.379,318.775 76.689,319.085 80.388,319.085 81.039,319.736 R180.2@81.039,322.75
I_SENSE_VDC_MID: C274.1 J26.97 R273.1 | length 34.4
  Top Layer w0.203: v2(57.302,327.548) 56.854,327.548 56.51,327.892 C274.1@56.51,329.37 58.205,329.37 62.084,333.248 63.343,333.248 64.676,334.581 79.134,334.581 81.502,332.212 R273.1@81.502,329.467
  Bottom Layer w0.203: v2(57.302,327.548) 58.365,327.548 J26.97@58.402,327.585
I_SENSE_VDC_NEG: C227.1 J26.95 R240.2 | length 40.8
  Top Layer w0.203: v2(56.602,326.785) C227.1@55.502,326.785 55.488,326.8 55.136,326.8 54.807,327.129 54.807,330.433 55.167,330.793 56.306,330.793 56.983,331.47 58.953,331.47 61.767,334.284 62.857,334.284 63.748,335.175 79.827,335.175 82.502,332.5 R240.2@82.502,329.467
  Bottom Layer w0.203: v2(56.602,326.785) J26.95@58.402,326.785
I_SN_L1+: L1.5 L1.6 U41.2
  other v1: 113.808,237.509 114.608,238.309 112.989,238.333 113.789,239.133 115.408,239.115 112.189,239.233 117.406,239.394 114.589,239.939 111.356,240.049 112.989,240.033 116.583,240.132 118.222,240.226 113.789,240.839 112.094,240.872 110.441,240.909 115.811,240.894 117.422,241.026 119.122,241.026 112.856,241.644 111.241,241.709 109.622,241.733 116.616,241.826 118.322,241.826 119.945,241.845 114.718,241.991 110.422,242.533 112.041,242.515 108.822,242.633 117.516,242.626 119.145,242.645 113.895,242.729 115.534,242.823 121.217,243.211 111.222,243.339 107.99,243.449 109.622,243.433 118.34,243.445 113.123,243.491 114.734,243.623 116.434,243.623 120.15,243.7 122.017,244.011 110.422,244.239 108.727,244.272 112.251,244.355 113.928,244.423 115.634,244.423 117.257,244.442 119.327,244.438 122.817,244.816 109.49,245.044 113.067,245.187 118.556,245.2 114.828,245.223 116.457,245.242 123.555,245.639 113.967,245.987 117.756,246 115.652,246.042 122.812,246.429 116.95,246.8 114.791,246.806 121.989,247.167 116.127,247.538 121.218,247.929 120.518,248.702 115.8,248.8 119.712,249.502 116.6,249.6 118.889,250.239 117.4,250.406
I_SN_L1-: C68.2 L4.AI RN1.4 TP35.1 U41.1 | length 25.6
  Top Layer w0.305: C68.2@104.965,238.923 108.084,238.923 115.105,231.903 125.997,231.903 126.4,231.5 RN1.4@126.4,230.378
  other v1: 43.9,203.798 45.9,203.8 47.9,203.798 49.9,203.8 39.1,204.8 42.7,204.8 43.9,205.248 45.9,205.25 47.9,205.248 49.9,205.25 39.478,206.05 42.274,206.161 40.9,206.7 43.9,206.798 45.9,206.8 47.9,206.798 49.9,206.8 105.158,231.271 106.753,231.328 104.335,232.009 105.981,232.09 107.653,232.128 103.609,232.809 105.158,232.828 106.881,232.89 108.995,233.069 102.838,233.571 104.433,233.628 106.058,233.628 108.176,233.893 102.015,234.309 103.662,234.39 107.03,234.406 105.333,234.428 110.558,234.566 101.209,235.109 102.839,235.128 104.562,235.19 107.793,235.177 106.211,235.229 109.738,235.39 111.295,235.389 100.409,235.909 102.033,235.928 103.739,235.928 106.973,236.001 105.411,236.129 110.476,236.213 101.233,236.728 102.933,236.728 109.33,236.725 104.544,236.86 105.8,237.2 110.093,237.496 102.133,237.528 108.511,237.549 103.772,237.622 106.7,238.1 109.273,238.32 102.949,238.36 107.711,238.449 108.473,239.22 106.999,239.238 107.706,239.974 106.228,240 105.405,240.738 106.935,240.737 106.112,241.474
I_SN_L2+: L2.5 L2.6 U47.1
  other v1: 121.725,152.496 120.7,153 119.697,153.476 122.232,153.476 123.2,153.983 118.877,154.3 122.9,155 118.077,155.2 122.2,155.933 117.406,156 116.7,156.756 121.381,156.756 120.581,157.656 116.6,157.71 119.8,158.433 117.075,158.7 118.935,159.1 117.91,159.155 107.9,172.3 107.129,173.062 108.676,173.081 106.306,173.8 107.905,173.843 109.5,173.9 107.082,174.581 105.5,174.6 108.729,174.662 110.3,174.719 106.276,175.381 107.906,175.4 109.529,175.482 111.05,175.519 107.1,176.2 108.706,176.219 110.279,176.282 107.9,177.019 109.456,177.019
I_SN_L2-: C69.2 L4.AII RN2.4 TP36.1 U47.2 | length 7.8
  Top Layer w0.5: C69.2@104.592,180.545 104.592,183.676 RN2.4@107.915,186.999
  other v1: 104.3,175.8 103.529,176.562 105.076,176.581 102.706,177.3 104.305,177.343 105.9,177.4 103.482,178.081 101.9,178.1 105.129,178.162 99.613,178.2 106.665,178.2 102.676,178.881 104.306,178.9 98.841,178.962 100.389,178.981 105.894,178.962 106.865,179.639 98.018,179.7 103.5,179.7 99.618,179.743 101.213,179.8 106.094,180.401 98.794,180.481 97.213,180.5 100.441,180.562 102.113,180.6 97.989,181.281 96.413,181.3 99.618,181.3 101.341,181.362 102.889,181.381 105.765,181.5 97.189,182.081 98.813,182.1 100.518,182.1 102.118,182.143 103.713,182.2 101.294,182.881 98.013,182.9 99.713,182.9 102.941,182.962 100.489,183.681 98.913,183.7 102.118,183.7 103.741,183.762 99.689,184.481 101.313,184.5 102.918,184.5 100.513,185.3 102.113,185.3 43.417,185.75 45.327,185.75 47.047,185.75 48.978,185.75 101.313,186.1 41.644,186.162 43.417,187.353 45.327,187.353 47.047,187.353 48.978,187.353 41.831,187.535 40.601,187.72 39.388,188.651 41.923,189.011 43.417,189.038 45.327,189.038 47.047,189.038 48.978,189.038 40.313,189.171 38.655,189.47 39.58,189.991 40.819,190.205 37.855,190.27 36.5,190.791 38.78,190.791 40.086,191.024 35.789,191.824 39.286,191.824
I_SN_L3+: L3.5 L3.6 U21.1
  other v1: 121.388,61.743 119.923,61.927 122.232,62.5 119.142,62.703 123.112,63.362 118.323,63.527 117.523,64.427 122.9,64.7 116.742,65.203 122.119,65.476 115.923,66.027 121.3,66.3 120.5,67.2 115.918,67.343 119.719,67.976 116.742,68.162 118.9,68.8 117.642,68.962 104.1,77.094 103.379,77.794 104.8,77.8 102.656,78.472 104.079,78.5 105.576,78.581 103.356,79.178 101.897,79.242 104.855,79.281 106.4,79.4 101.2,79.913 102.597,79.948 104.132,79.959 105.679,80.1 107.213,80.264 100.453,80.595 101.9,80.619 103.373,80.729 104.956,80.778 106.579,80.9 108.026,81.051 101.153,81.301 102.676,81.4 104.197,81.548 105.856,81.578 107.355,81.681 108.843,81.839 101.929,82.082 103.5,82.219 105.097,82.348 106.632,82.359 108.179,82.5 109.626,82.652 102.804,82.871 104.4,83.019 105.873,83.129 107.456,83.178 108.979,83.3 106.697,83.948 108.256,83.978 114.449,136.123 113.649,136.923 115.225,136.904 114.425,137.704 116.049,137.723 112.852,137.801 115.249,138.523 116.949,138.523 112.052,138.601 113.628,138.582 117.725,139.304 116.149,139.323 112.828,139.382 114.452,139.401 116.925,140.104 118.549,140.123 113.652,140.201 115.352,140.201 117.749,140.923 119.349,140.923 116.128,140.982 114.552,141.001 112.055,141.096 118.549,141.723 115.328,141.782 116.952,141.801 111.284,141.858 112.831,141.876 110.461,142.596 116.152,142.601 117.752,142.601 112.06,142.639 113.655,142.696 111.237,143.376 109.655,143.396 116.952,143.401 112.884,143.458 114.455,143.515 110.431,144.176 112.061,144.196 113.684,144.277 115.218,144.315 111.255,144.996 112.861,145.015 114.446,145.077 112.055,145.815 113.623,145.815 112.818,146.615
